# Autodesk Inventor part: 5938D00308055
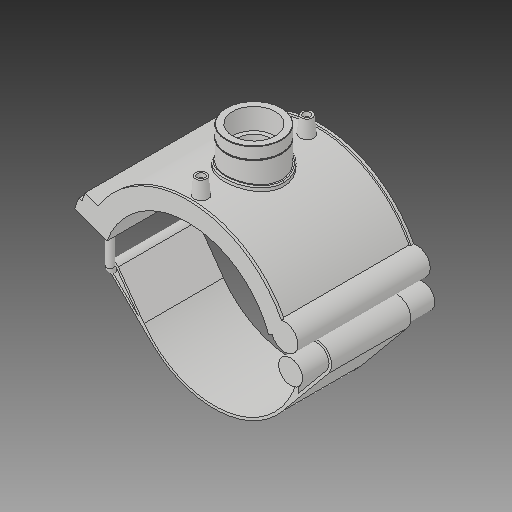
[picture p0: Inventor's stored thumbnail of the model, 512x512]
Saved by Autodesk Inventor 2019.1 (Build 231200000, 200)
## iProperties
Created: 2017-07
Part Number: 5938D00308055
Material: Generic
Description: PLASSON TRANSITION SADDLE 8''DIPS x 2"NPT
Document SubType Name: Modeling
Designer: KIM
Density: 1 g/cm^3
Appearance: Default
Author: KIM
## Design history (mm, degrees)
derived "5938D.ipt"
feature "Solid1::5938D.ipt"
tag "TaggingFeature1"
body "Solid1"
other parameters: "d0" = 228.9, "d1" = 274.68, "d2" = 449.58, "d3" = 57.225, "d4" = 176.022, "d5" = 0, "d40" = 142.8336, "d41" = 79.3184, "d43" = 0, "d45" = 0, "d47" = 184.076, "d48" = 73.6528, "d50" = 0, "d78" = 159.34, "d79" = 15, "d80" = 70.4088, "d82" = 5 deg, "d84" = 4, "d85" = 14, "d86" = 0, "d87" = 3, "d88" = 0, "d96" = 280.1736, "d97" = 3.52044, "d98" = 0, "d102" = 1.69968, "d103" = 56.656, "d104" = 28.0416, "d105" = 0, "d106" = 45.3248, "d108" = 0, "d109" = -15.57867, "d111" = 0.5, "d112" = 0.5, "d113" = 0, "d114" = 0.5, "d117" = 0.56656, "d120" = 140 deg, "d121" = 24.228, "d122" = 20 deg, "d123" = 1098.72, "d124" = 164.808, "d126" = 0, "d143" = 235.767, "d145" = 35.21538, "d149" = 3.4335, "d150" = 38.73692, "d153" = 176.022, "d154" = 0, "d156" = 137.34, "d157" = 160 deg, "d159" = 9.156, "d161" = 3.4335, "d162" = 105.6132, "d163" = 0, "d164" = 114.45, "d167" = 22.89, "d168" = 133.99024, "d170" = 3.4335, "d172" = 0, "d173" = 1, "d175" = 114.45, "d176" = 20 deg, "d177" = 16.023, "d178" = 45.78, "d180" = 0, "d183" = 18.312, "d184" = 12.8184, "d185" = 57.20715, "d186" = 57.20715, "d187" = 137.34, "d188" = 13.734, "d189" = 16.023, "d190" = 0, "d191" = 164.808, "d193" = 9.156, "d194" = 4.69245, "d195" = 90 deg, "d197" = 0, "d199" = 0, "d_" = 228.9, "B_" = 179.832, "H_" = 46.736, "L_" = 176.022, "d_t" = 6, "G_" = 56.656, "d148" = 3.4335, "d160" = 3.4335, "d169" = 3.4335, "d192" = 9.156
